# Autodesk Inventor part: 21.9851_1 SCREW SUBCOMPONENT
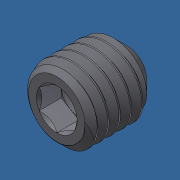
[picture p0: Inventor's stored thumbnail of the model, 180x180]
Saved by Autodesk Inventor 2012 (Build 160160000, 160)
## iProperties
Created: 2014-01
Part Number: 21.9851_1 SCREW SUBCOMPONENT
Material: Stainless Steel
Document SubType Name: Modeling
Designer: Admin
Density: 7.75 g/cm^3
Description: SUBCOMPONENT
Stock Number: SUBCOMPONENT
Mass: 0.48453 g
Surface Area: 1.48393 cm^2
Volume: 0.06252 cm^3
Author: Admin
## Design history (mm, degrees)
node "90251A1621"
node "Base1"
body "Solid1"
